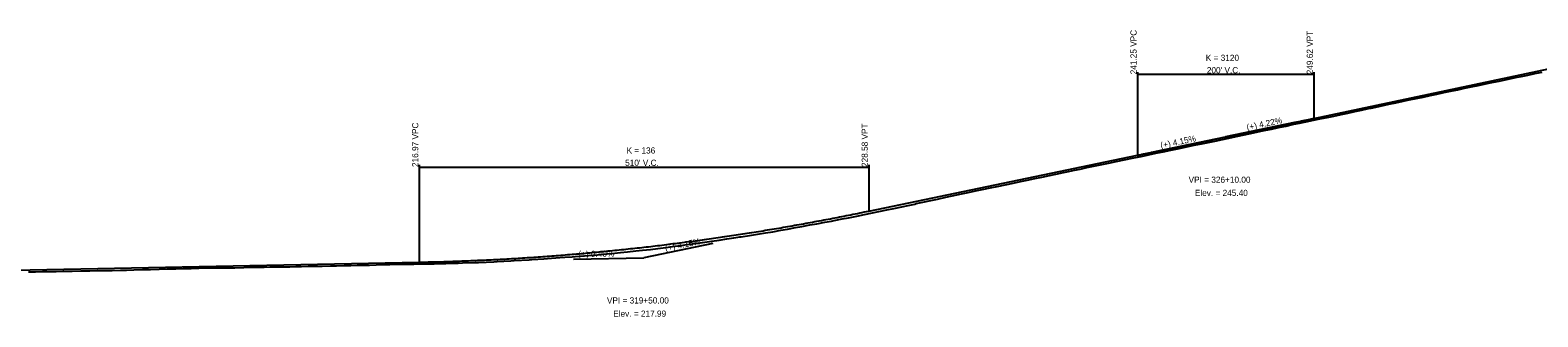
# Model space of a CAD drawing. Extents: x 1876258 to 1932803, y 754739 to 837911.
# Drawn here: x 1909617 to 1911327, y 828486 to 828811 of the extents above; entities that cross this region are included whole.
import ezdxf

# ---------------------------------------------------------------- set-up
doc = ezdxf.new("R2010")
doc.units = 0
for name, color, linetype in [('RD_DDB_GradeTX', 7, 'Continuous'), ('RD_DDB_Profile_EX', 7, 'Continuous'), ('RD_DDB_Profile_Lbl', 7, 'Continuous'), ('RD_DDB_Profile_PR', 7, 'Continuous'), ('RD_DDB_StripGrade', 7, 'Continuous'), ('RD_DDB_VCLbl', 7, 'Continuous')]:
    doc.layers.add(name, color=color, linetype=linetype)

msp = doc.modelspace()

# ---------------------------------------------------------------- linework, layer by layer
at = {"layer": 'RD_DDB_GradeTX'}
for p, q in [((1910894.8, 828673.5), (1910973.1, 828689.8)), ((1911051.4, 828706.3), (1910973.1, 828689.8)), ((1910233.1, 828551.2), (1910313.1, 828552.8)), ((1910391.4, 828569), (1910313.1, 828552.8))]:
    msp.add_line(p, q, dxfattribs=at)
at = {"layer": 'RD_DDB_Profile_EX'}
for points in [[(1910858.1, 828663.7), (1910867, 828665.6), (1910868.9, 828666), (1910877.3, 828667.8), (1910885.5, 828669.5), (1910893.9, 828671.4), (1910902.4, 828673.1), (1910911, 828674.9), (1910920.5, 828676.8), (1910928.8, 828678.5), (1910937.5, 828680.3), (1910945.7, 828682.1), (1910953.3, 828683.6), (1910962.8, 828685.5), (1910969.5, 828687), (1910976.9, 828688.5), (1910984.9, 828690.2), (1910994.3, 828692.2), (1911001.3, 828693.7), (1911009.7, 828695.5), (1911016.9, 828697), (1911025.1, 828698.7), (1911033.1, 828700.5), (1911041.3, 828702.2), (1911048.8, 828703.8), (1911056.9, 828705.5), (1911064.2, 828707), (1911072.8, 828708.8), (1911080.2, 828710.3), (1911088.3, 828711.9), (1911095.9, 828713.5), (1911104.2, 828715.4), (1911111.8, 828716.9), (1911119.9, 828718.6), (1911127.3, 828720.2), (1911135.3, 828722), (1911138.1, 828722.6), (1911140.1, 828723), (1911148.6, 828724.7), (1911158.2, 828726.9), (1911166.1, 828728.6), (1911174.4, 828730.3), (1911181.5, 828731.8), (1911189.3, 828733.4), (1911197.3, 828735.1), (1911205.3, 828736.8), (1911212.9, 828738.4), (1911220.7, 828740.1), (1911228.3, 828741.7), (1911236.5, 828743.4), (1911244, 828745), (1911251.8, 828746.6), (1911259.5, 828748.2), (1911267.9, 828750), (1911275.2, 828751.5), (1911283.5, 828753.3), (1911290.4, 828754.7), (1911298.7, 828756.5), (1911304, 828757.5), (1911308.5, 828758.5), (1911316.1, 828760.1), (1911324.1, 828761.8), (1911332.2, 828763.5)], [(1910046.2, 828545.4), (1910052, 828545.6), (1910058, 828545.7), (1910060.4, 828545.8), (1910075.1, 828546), (1910077.4, 828546.1), (1910088.4, 828546.3), (1910092.5, 828546.5), (1910102.4, 828546.6), (1910107.1, 828546.8), (1910121.6, 828547.3), (1910125.5, 828547.5), (1910142.7, 828548.2), (1910146.6, 828548.4), (1910162.2, 828549.3), (1910165.8, 828549.5), (1910182.8, 828550.5), (1910186, 828550.7), (1910199.5, 828551.6), (1910203.7, 828551.9), (1910217.7, 828552.9), (1910223.2, 828553.3), (1910231.5, 828553.8), (1910234.9, 828554), (1910240.8, 828554.5), (1910255, 828555.5), (1910260.5, 828556), (1910271.3, 828557), (1910276.6, 828557.5), (1910286.6, 828558.6), (1910294.6, 828559.4), (1910303.9, 828560.4), (1910311.4, 828561.2), (1910320.6, 828562.2), (1910328.7, 828563.1), (1910337.9, 828564.2), (1910345.5, 828565.3), (1910354.6, 828566.6), (1910362.2, 828567.6), (1910371.8, 828569), (1910379.5, 828570.1), (1910390.3, 828571.6), (1910398.4, 828572.7), (1910407.3, 828574.1), (1910415.1, 828575.3), (1910422, 828576.3), (1910423.4, 828576.4), (1910432.8, 828577.9), (1910442.1, 828579.4), (1910451, 828580.9), (1910459.2, 828582.3), (1910468.3, 828583.9), (1910476, 828585.2), (1910485.1, 828586.9), (1910492.2, 828588.2), (1910501.3, 828589.9), (1910509.2, 828591.3), (1910518.3, 828593), (1910525.9, 828594.3), (1910528.8, 828594.9), (1910537.9, 828596.7), (1910545.3, 828598.2), (1910554.6, 828600), (1910563.3, 828601.7), (1910572.4, 828603.6), (1910579.6, 828605.2), (1910588.7, 828607), (1910596.5, 828608.6), (1910605.9, 828610.6), (1910613.1, 828612.1), (1910620.3, 828613.7), (1910622, 828614.1), (1910629.4, 828615.7), (1910638.7, 828617.6), (1910646.2, 828619.2), (1910655.7, 828621.3), (1910663, 828622.9), (1910673.6, 828625.1), (1910681.1, 828626.7), (1910689.5, 828628.5), (1910697, 828630), (1910706.1, 828631.9), (1910713.8, 828633.5), (1910723, 828635.4), (1910731.9, 828637.3), (1910740.5, 828639.1), (1910748.1, 828640.7), (1910756.8, 828642.5), (1910764.5, 828644.1), (1910773.2, 828646.1), (1910780.3, 828647.7), (1910789.1, 828649.5), (1910794.9, 828650.6), (1910801.8, 828652.1), (1910808, 828653.4), (1910815.6, 828655), (1910823.1, 828656.5), (1910832.6, 828658.5), (1910840.2, 828660), (1910848.9, 828661.8), (1910858.1, 828663.7)], [(1909614.7, 828536.8), (1909622.7, 828536.9), (1909630.6, 828537), (1909637.3, 828537.2), (1909646.2, 828537.3), (1909653.9, 828537.5), (1909664.3, 828537.6), (1909674.3, 828537.8), (1909684.2, 828538), (1909692.9, 828538.1), (1909701.4, 828538.3), (1909709.9, 828538.4), (1909719.2, 828538.6), (1909726.1, 828538.7), (1909734.3, 828539), (1909744.1, 828539.3), (1909753.4, 828539.4), (1909762.9, 828539.7), (1909771.8, 828540), (1909782, 828540.2), (1909790.2, 828540.4), (1909799.3, 828540.5), (1909808, 828540.8), (1909821.1, 828541.1), (1909829.6, 828541.3), (1909839.6, 828541.3), (1909848.9, 828541.4), (1909859.2, 828541.7), (1909865.9, 828541.9), (1909876, 828542), (1909882.3, 828542.2), (1909888.8, 828542.3), (1909894.8, 828542.4), (1909904.2, 828542.5), (1909911.4, 828542.5), (1909918.3, 828542.7), (1909924.4, 828542.8), (1909932.2, 828543), (1909940.7, 828543.2), (1909948.1, 828543.3), (1909957.3, 828543.6), (1909964.2, 828543.7), (1909972.9, 828543.9), (1909980.5, 828544), (1909987.9, 828544.2), (1909996.1, 828544.3), (1910001.8, 828544.4), (1910009.1, 828544.6), (1910017.9, 828544.9), (1910024.8, 828545), (1910032.9, 828545.3), (1910040.2, 828545.3), (1910046.2, 828545.4)]]:
    msp.add_lwpolyline(points, dxfattribs=at)
at = {"layer": 'RD_DDB_Profile_PR'}
for p, q in [((1911073.1, 828710.9), (1911373.1, 828774.1)), ((1910568.1, 828605.7), (1910873.1, 828669)), ((1908933.1, 828525.2), (1910058.1, 828547.7))]:
    msp.add_line(p, q, dxfattribs=at)
for points in [[(1910873.1, 828669), (1910877.1, 828669.9), (1910881.1, 828670.7), (1910885.1, 828671.5), (1910889.1, 828672.4), (1910893.1, 828673.2), (1910897.1, 828674), (1910901.1, 828674.9), (1910905.1, 828675.7), (1910909.1, 828676.5), (1910913.1, 828677.4), (1910917.1, 828678.2), (1910921.1, 828679), (1910925.1, 828679.9), (1910929.1, 828680.7), (1910933.1, 828681.5), (1910937.1, 828682.4), (1910941.1, 828683.2), (1910945.1, 828684), (1910949.1, 828684.9), (1910953.1, 828685.7), (1910957.1, 828686.5), (1910961.1, 828687.4), (1910965.1, 828688.2), (1910969.1, 828689), (1910973.1, 828689.9), (1910977.1, 828690.7), (1910981.1, 828691.6), (1910985.1, 828692.4), (1910989.1, 828693.2), (1910993.1, 828694.1), (1910997.1, 828694.9), (1911001.1, 828695.7), (1911005.1, 828696.6), (1911009.1, 828697.4), (1911013.1, 828698.3), (1911017.1, 828699.1), (1911021.1, 828699.9), (1911025.1, 828700.8), (1911029.1, 828701.6), (1911033.1, 828702.5), (1911037.1, 828703.3), (1911041.1, 828704.1), (1911045.1, 828705), (1911049.1, 828705.8), (1911053.1, 828706.7), (1911057.1, 828707.5), (1911061.1, 828708.4), (1911065.1, 828709.2), (1911069.1, 828710), (1911073.1, 828710.9)], [(1910058.1, 828547.7), (1910068.3, 828547.9), (1910078.5, 828548.1), (1910088.7, 828548.4), (1910098.9, 828548.8), (1910109.1, 828549.2), (1910119.3, 828549.6), (1910129.5, 828550), (1910139.7, 828550.5), (1910149.9, 828551), (1910160.1, 828551.6), (1910170.3, 828552.2), (1910180.5, 828552.9), (1910190.7, 828553.5), (1910200.9, 828554.3), (1910211.1, 828555), (1910221.3, 828555.8), (1910231.5, 828556.7), (1910241.7, 828557.5), (1910251.9, 828558.4), (1910262.1, 828559.4), (1910272.3, 828560.4), (1910282.5, 828561.4), (1910292.7, 828562.5), (1910302.9, 828563.6), (1910313.1, 828564.7), (1910323.3, 828565.9), (1910333.5, 828567.1), (1910343.7, 828568.4), (1910353.9, 828569.7), (1910364.1, 828571), (1910374.3, 828572.4), (1910384.5, 828573.8), (1910394.7, 828575.2), (1910404.9, 828576.7), (1910415.1, 828578.2), (1910425.3, 828579.8), (1910435.5, 828581.4), (1910445.7, 828583), (1910455.9, 828584.7), (1910466.1, 828586.4), (1910476.3, 828588.2), (1910486.5, 828590), (1910496.7, 828591.8), (1910506.9, 828593.7), (1910517.1, 828595.6), (1910527.3, 828597.5), (1910537.5, 828599.5), (1910547.7, 828601.5), (1910557.9, 828603.6), (1910568.1, 828605.7)]]:
    msp.add_spline(points, degree=3, dxfattribs=at)
at = {"layer": 'RD_DDB_VCLbl'}
for p, q in [((1910873.1, 828763.4), (1910873.1, 828669)), ((1910873.1, 828760.9), (1911073.1, 828760.9)), ((1911073.1, 828763.4), (1911073.1, 828710.9)), ((1910058.1, 828658.2), (1910058.1, 828547.7)), ((1910058.1, 828655.7), (1910568.1, 828655.7)), ((1910568.1, 828658.2), (1910568.1, 828605.7))]:
    msp.add_line(p, q, dxfattribs=at)

# ---------------------------------------------------------------- texts
at = {"layer": 'RD_DDB_GradeTX'}
for s, rotation, p in [('(+) 4.22%', 11.9068, (1910997.8, 828697.1)), ('(+) 4.15%', 11.7308, (1910899.9, 828676.6)), ('(+) 4.15%', 11.7308, (1910337.8, 828559.9)), ('(+) 0.40%', 1.1458, (1910238.7, 828553.3))]:
    msp.add_text(s, height=7, rotation=rotation, dxfattribs=at).set_placement(p)
at = {"layer": 'RD_DDB_Profile_Lbl'}
for s, p in [('VPI = 326+10.00', (1910931.1, 828637.8)), ('Elev. = 245.40', (1910938.2, 828622.8)), ('VPI = 319+50.00', (1910271.1, 828500.8)), ('Elev. = 217.99', (1910278.2, 828485.8))]:
    msp.add_text(s, height=7, dxfattribs=at).set_placement(p)
at = {"layer": 'RD_DDB_StripGrade'}
for s, p in [('241.25 VPC', (1910872.1, 828760.9)), ('249.62 VPT', (1911072.1, 828760.9)), ('216.97 VPC', (1910057.1, 828655.7)), ('228.58 VPT', (1910567.1, 828655.7))]:
    msp.add_text(s, height=7, rotation=90, dxfattribs=at).set_placement(p)
at = {"layer": 'RD_DDB_VCLbl'}
for s, p in [('K = 3120', (1910950.6, 828776.1)), ("200' V.C.", (1910951.8, 828762.1)), ('K = 136', (1910293.4, 828671)), ("510' V.C.", (1910291.8, 828657))]:
    msp.add_text(s, height=7, dxfattribs=at).set_placement(p)

doc.saveas('drawing.dxf')
